// Mitsubishi GX Works2 project: MC-42MR-8MTS-F700-H3G-A-LAN   PLC: FX3G

PROGRAM MAIN
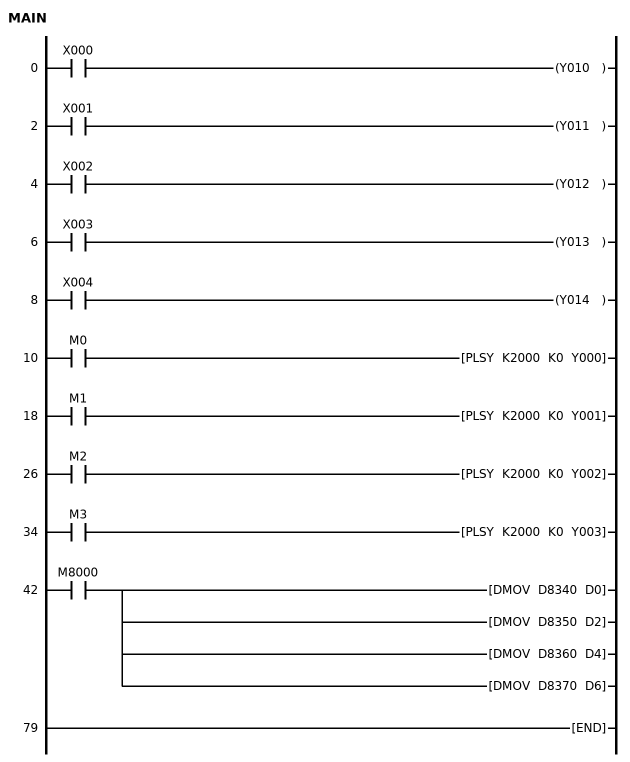
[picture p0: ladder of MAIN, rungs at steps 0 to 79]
0     LD      X000
      OUT     Y010
2     LD      X001
      OUT     Y011
4     LD      X002
      OUT     Y012
6     LD      X003
      OUT     Y013
8     LD      X004
      OUT     Y014
10    LD      M0
      PLSY    K2000 K0 Y000
18    LD      M1
      PLSY    K2000 K0 Y001
26    LD      M2
      PLSY    K2000 K0 Y002
34    LD      M3
      PLSY    K2000 K0 Y003
42    LD      M8000
      DMOV    D8340 D0
      DMOV    D8350 D2
      DMOV    D8360 D4
      DMOV    D8370 D6
79    END
END_PROGRAM
